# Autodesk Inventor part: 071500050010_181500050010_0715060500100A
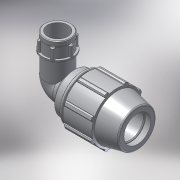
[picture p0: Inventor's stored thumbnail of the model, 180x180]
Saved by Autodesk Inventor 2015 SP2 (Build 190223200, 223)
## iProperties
Created: 2017-02
Part Number: 071500050010_181500050010_0715060500100A
Material: PVC-Piping
Description: PLASSON 90° ELBOW FEMALE ADAPTOR 50-1"
Document SubType Name: Modeling
Designer: KIM
Mass: 92.6774 g
Surface Area: 199.44 cm^2
Volume: 66.1981 cm^3
Density: 1.4 g/cm^3
Appearance: Smooth - White
Author: KIM
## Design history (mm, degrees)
derived "07150.ipt"
feature "Solid1::07150.ipt"
tag "TaggingFeature1"
body "Solid1"
other parameters: "d4" = 11.08333, "d5" = 33.25, "d7" = 96, "d9" = 19, "d11" = 4.43333, "d13" = 120 deg, "d15" = 12 deg, "d16" = 83.52, "d18" = 2.5, "d19" = 35 deg, "d20" = 17.5 deg, "d21" = 89.28, "d23" = 0, "d25" = 360 deg, "d27" = 1.92, "d33" = 1, "d42" = 49.21, "d43" = 2.88, "d46" = 1.5, "d51" = 133, "d68" = 4.43333, "d72" = 57, "d73" = 39.3783, "d74" = 21, "d75" = 45.28505, "d76" = 30.291, "d77" = 23.1, "d79" = 12.1164, "d80" = 0.90873, "d83" = 0, "d84" = 0, "d91" = 72, "d93" = 93, "d94" = 30.291, "d95" = 21.2037, "d96" = 13.3, "d97" = 50 deg, "d98" = 27.2619, "d99" = 0.5, "d100" = 0.5, "d101" = 7, "d102" = 39.3783, "d103" = 17.85, "d104" = 0, "d108" = 360 deg, "d110" = 1.18135, "E_" = 96, "A_" = 133, "l_" = 93, "l_2" = 21, "A_1" = 57, "Rp_" = 30.291, "d105" = 5.90674
